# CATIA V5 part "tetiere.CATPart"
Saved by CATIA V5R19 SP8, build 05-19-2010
Part number: tetiere
Revision: ANY
Definition: UNKNOWN
Nomenclature: tetiere
Source: Unknown
Bounding box of the stored display mesh (mm): x -11 to 11, y -115 to 115, z -1.5 to 4.5
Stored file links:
  D:\Documents\1_Travail\1 - ac-limoges.fr\ac-limoges.fr\Emmanuel Maynard - STI2D_Turgot\2 -2I2D\2_SEQUENCE_Serrure_Biométrique\5-Spé_ITEC\Serrure_Bio_Eleve\tetiere.CATPart
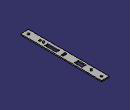
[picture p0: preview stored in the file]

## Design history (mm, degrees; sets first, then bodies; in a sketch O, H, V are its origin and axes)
Body1 "Extrusion2" (main body)
  Solid1: solid without history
